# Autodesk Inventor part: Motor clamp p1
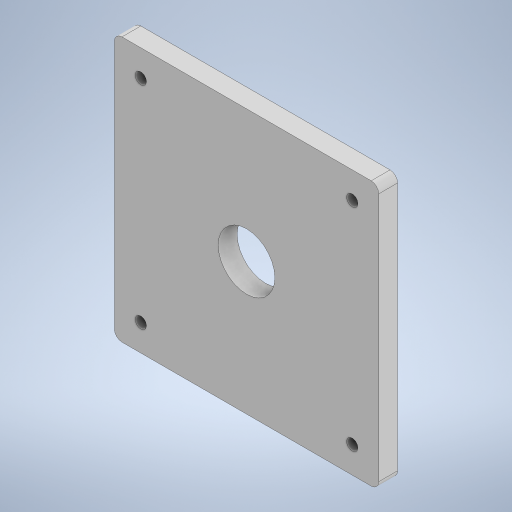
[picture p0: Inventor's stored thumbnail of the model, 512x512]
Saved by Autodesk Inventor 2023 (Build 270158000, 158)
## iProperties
Created: 2022-06
Part Number: Motor clamp p1
Material: Generic
Document SubType Name: Modeling
Designer: prana_p9lsmih
Density: 1 g/cm^3
Appearance: Default
Author: prana_p9lsmih
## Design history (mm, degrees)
sketch "Sketch1"
  geometry: L1 (0, 0)-(70, 0); L2 (70, 0)-(70, 70); L3 (70, 70)-(0, 70); L4 (0, 70)-(0, 0)
  constraints: 8 end point, 3 perpendicular, 1 horizontal
  dimensions: "d0" = 70 distance of L1.start L1.end; "d1" = 70 distance of L1.end L2.end
extrude "Extrusion1" new body sketch "Sketch1" distance "d2" = 5; taper "d3" = 0 deg
sketch "Sketch2"
  geometry: L1 (70, 70)-(0, 70) reference; L2 (70, 0)-(70, 70) reference; 2 further points
  dimensions: "d4" = 35 distance from line of L1 point (35, 35); "d5" = 35 distance from line of L2 point (35, 35)
hole "Hole1" sketch "Sketch2" at (35, 35) diameter "d6" = 15; stored, may be unused: countersink angle "d10" = 90 deg, drill point angle "d12" = 118 deg; dims "d7" = 6, "d8" = 4, "d9" = 2, "d11" = 8
fillet "Fillet1" dims "d13" = 2
sketch "Sketch3"
  geometry: L1 (2, 0)-(68, 0) reference; L2 (70, 2)-(70, 68) reference; 2 further points
  dimensions: "d14" = 7 distance from line of L1 point (63, 7); "d15" = 7 distance from line of L2 point (63, 7)
hole "Hole2" sketch "Sketch3" at (63, 7) diameter "d16" = 3; stored, may be unused: countersink angle "d20" = 90 deg, drill point angle "d22" = 118 deg; dims "d17" = 6, "d18" = 4, "d19" = 2, "d21" = 8
sketch "Sketch4"
  geometry: L1 (2, 0)-(68, 0) reference; L2 (0, 68)-(0, 2) reference; L3 (68, 70)-(2, 70) reference; L4 (70, 2)-(70, 68) reference; 4 further points
  dimensions: "d23" = 7 distance from line of L1 point (7, 7); "d24" = 7 distance from line of L2 point (7, 7); "d25" = 7 distance from line of L2 point (7, 63); "d26" = 7 distance from line of L3 point (7, 63); "d27" = 7 distance from line of L3 point (63, 63); "d28" = 7 distance from line of L4 point (63, 63)
hole "Hole3" sketch "Sketch4" at (7, 7), (7, 63), (63, 63) diameter "d29" = 3; stored, may be unused: countersink angle "d33" = 90 deg, drill point angle "d35" = 118 deg; dims "d30" = 6, "d31" = 4, "d32" = 2, "d34" = 8
sketch "Sketch5"
  geometry: L1 (0, 66)-(0, 0) reference; L2 (0, -2)-(5, -2) reference; 1 further point
  dimensions: "d36" = 2.5 distance from line of L1 point (2.5, 33); "d37" = 35 distance from line of L2 point (2.5, 33)
hole "Hole4" sketch "Sketch5" at (2.5, 33) diameter "d38" = 2; stored, may be unused: countersink angle "d42" = 90 deg, drill point angle "d44" = 118 deg; dims "d39" = 6, "d40" = 4, "d41" = 2, "d43" = 10
body "Solid1"
